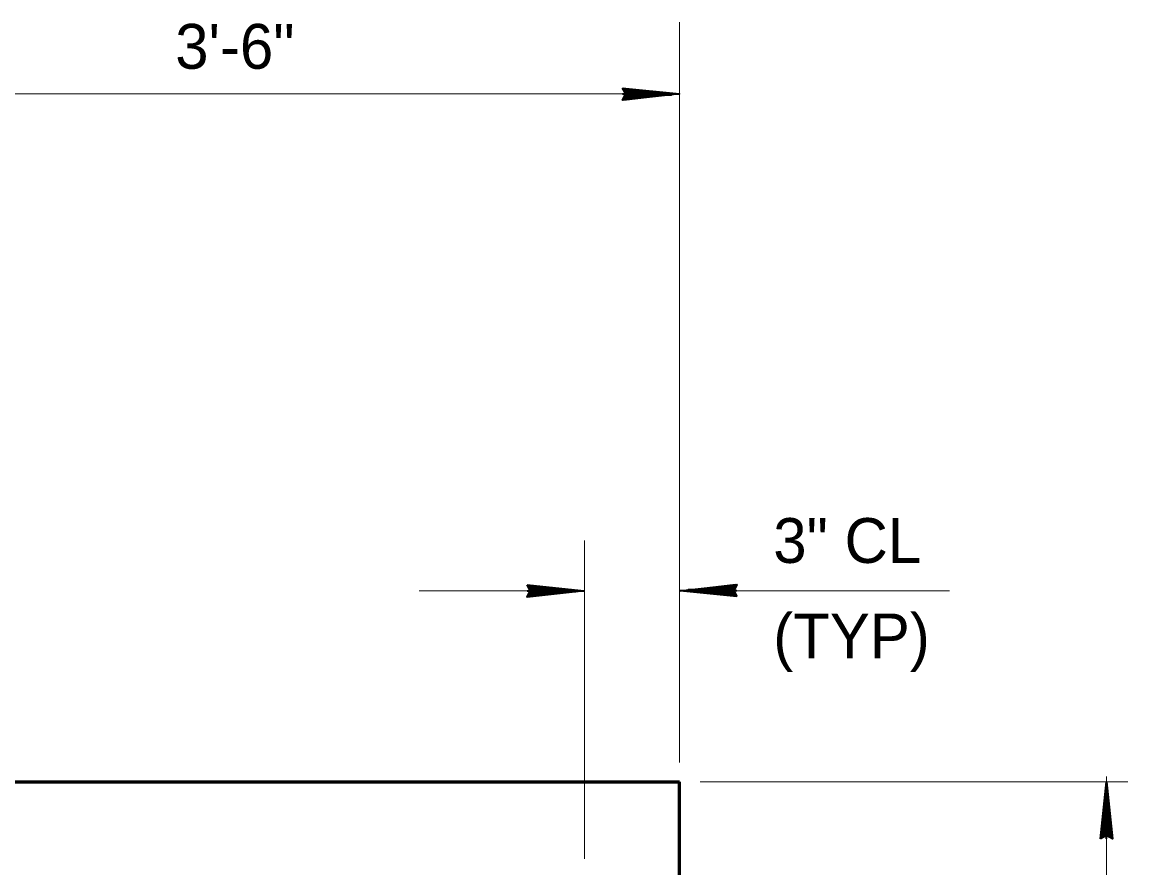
# Model space of a CAD drawing. Extents: x 14.14 to 17.34, y -1.61 to 0.38.
# Drawn here: x 16.3775 to 16.583, y 0.0521 to 0.2092 of the extents above; entities that cross this region are included whole.
import ezdxf

# ---------------------------------------------------------------- set-up
doc = ezdxf.new("R2010")
doc.units = 0
doc.header["$LTSCALE"] = 0.0033
doc.layers.add('1', color=7, linetype='Continuous', lineweight=40)

msp = doc.modelspace()

# ---------------------------------------------------------------- linework, layer by layer
at = {"layer": '1', "lineweight": 13}
for p, q in [((16.499667, 0.071667), (16.499667, 0.20925)), ((16.000417, 0.195917), (16.499083, 0.195917)), ((16.482, 0.05375), (16.482, 0.112917)), ((16.45125, 0.103583), (16.472083, 0.103583)), ((16.5095, 0.103583), (16.549833, 0.103583)), ((16.5035, 0.068083), (16.583, 0.068083)), ((16.579, 0.069083), (16.579, -0.01425))]:
    msp.add_line(p, q, dxfattribs=at)
at = {"layer": '1', "lineweight": 35}
for p, q in [((16.489083, 0.195917), (16.499667, 0.195917)), ((16.48925, 0.19525), (16.496583, 0.196)), ((16.489333, 0.196917), (16.497167, 0.196)), ((16.489333, 0.196917), (16.497167, 0.196)), ((16.489333, 0.196833), (16.497167, 0.196)), ((16.489333, 0.19675), (16.497167, 0.195917)), ((16.489333, 0.19675), (16.497167, 0.19575)), ((16.489333, 0.195083), (16.496667, 0.195917)), ((16.489333, 0.195), (16.496667, 0.19575)), ((16.489333, 0.194833), (16.496667, 0.195667)), ((16.471333, 0.103583), (16.481917, 0.103583)), ((16.4715, 0.102917), (16.478833, 0.103667)), ((16.471583, 0.104583), (16.479417, 0.103667)), ((16.471583, 0.104583), (16.479417, 0.103667)), ((16.471583, 0.1045), (16.479417, 0.103667)), ((16.471583, 0.104417), (16.479417, 0.103583)), ((16.471583, 0.104417), (16.479417, 0.103417)), ((16.471583, 0.10275), (16.478917, 0.103583)), ((16.471583, 0.102667), (16.478917, 0.103417)), ((16.471583, 0.1025), (16.478917, 0.103333)), ((16.510333, 0.103583), (16.49975, 0.103583)), ((16.510083, 0.10275), (16.50225, 0.10375)), ((16.510083, 0.10275), (16.50225, 0.103583)), ((16.510083, 0.102583), (16.50225, 0.1035)), ((16.510083, 0.102583), (16.50225, 0.1035)), ((16.510083, 0.102667), (16.50225, 0.1035)), ((16.510083, 0.104667), (16.50275, 0.103833)), ((16.510083, 0.1045), (16.50275, 0.10375)), ((16.510083, 0.104417), (16.50275, 0.103583)), ((16.510167, 0.10425), (16.502833, 0.1035)), ((16.579, 0.0575), (16.579, 0.068083)), ((16.578, 0.05775), (16.578917, 0.065583)), ((16.578, 0.05775), (16.578917, 0.065583)), ((16.578083, 0.05775), (16.578917, 0.065583)), ((16.578167, 0.05775), (16.579, 0.065583)), ((16.578167, 0.05775), (16.579167, 0.065583)), ((16.579667, 0.057667), (16.578917, 0.065)), ((16.579833, 0.05775), (16.579, 0.065083)), ((16.579917, 0.05775), (16.579167, 0.065083)), ((16.580083, 0.05775), (16.57925, 0.065083))]:
    msp.add_line(p, q, dxfattribs=at)
for points in [[(16.489083, 0.197), (16.499667, 0.195917), (16.489083, 0.19475), (16.489667, 0.195917)], [(16.489833, 0.196), (16.4945, 0.196083), (16.4945, 0.196), (16.493583, 0.196), (16.489833, 0.196083), (16.492833, 0.196167), (16.489667, 0.19625), (16.491917, 0.196333), (16.489667, 0.196417), (16.493167, 0.196167), (16.497833, 0.196), (16.496917, 0.19575), (16.498167, 0.19575), (16.489833, 0.19575), (16.49225, 0.195583), (16.489667, 0.195583), (16.495, 0.196), (16.489667, 0.195333)], [(16.471333, 0.104667), (16.481917, 0.103583), (16.471333, 0.102417), (16.471917, 0.103583)], [(16.472083, 0.103667), (16.47675, 0.10375), (16.47675, 0.103667), (16.475833, 0.103667), (16.472083, 0.10375), (16.475083, 0.103833), (16.471917, 0.103917), (16.474167, 0.104), (16.471917, 0.104083), (16.475417, 0.103833), (16.480083, 0.103667), (16.479167, 0.103417), (16.480417, 0.103417), (16.472083, 0.103417), (16.4745, 0.10325), (16.471917, 0.10325), (16.47725, 0.103667), (16.471917, 0.103)], [(16.510333, 0.1025), (16.49975, 0.103583), (16.510333, 0.10475), (16.50975, 0.103583)], [(16.509583, 0.1035), (16.504917, 0.103417), (16.504917, 0.1035), (16.505833, 0.1035), (16.509583, 0.103417), (16.506583, 0.103333), (16.50975, 0.10325), (16.5075, 0.103167), (16.50975, 0.103083), (16.50625, 0.103333), (16.501583, 0.1035), (16.5025, 0.10375), (16.50125, 0.10375), (16.509583, 0.10375), (16.507167, 0.103917), (16.50975, 0.103917), (16.504417, 0.1035), (16.50975, 0.104167)], [(16.577917, 0.0575), (16.579, 0.068083), (16.580167, 0.0575), (16.579, 0.058083)], [(16.578917, 0.05825), (16.578833, 0.062917), (16.578917, 0.062917), (16.578917, 0.062), (16.578833, 0.05825), (16.57875, 0.06125), (16.578667, 0.058083), (16.578583, 0.060333), (16.5785, 0.058083), (16.57875, 0.061583), (16.578917, 0.06625), (16.579167, 0.065333), (16.579167, 0.066583), (16.579167, 0.05825), (16.579333, 0.060667), (16.579333, 0.058083), (16.578917, 0.063417), (16.579583, 0.058083)]]:
    msp.add_lwpolyline(points, close=True, dxfattribs=at)
for points in [[(16.489833, 0.196), (16.489417, 0.19675), (16.489667, 0.1965), (16.489833, 0.196167), (16.490083, 0.19625), (16.489917, 0.196583), (16.48975, 0.195833), (16.489583, 0.195333), (16.489333, 0.194917)], [(16.472083, 0.103667), (16.471667, 0.104417), (16.471917, 0.104167), (16.472083, 0.103833), (16.472333, 0.103917), (16.472167, 0.10425), (16.472, 0.1035), (16.471833, 0.103), (16.471583, 0.102583)], [(16.509583, 0.1035), (16.51, 0.10275), (16.50975, 0.103), (16.509583, 0.103333), (16.509333, 0.10325), (16.5095, 0.102917), (16.509667, 0.103667), (16.509833, 0.104167), (16.510083, 0.104583)], [(16.578917, 0.05825), (16.578167, 0.057833), (16.578417, 0.058083), (16.57875, 0.05825), (16.578667, 0.0585), (16.578333, 0.058333), (16.579083, 0.058167), (16.579583, 0.058), (16.58, 0.05775)]]:
    msp.add_lwpolyline(points, dxfattribs=at)
at = {"layer": '1', "lineweight": 60}
for points in [[(16.333, 0.17225), (16.333, 0.068083), (16.499667, 0.068083)], [(15.999667, -0.01525), (16.499667, -0.01525), (16.499667, 0.068083)]]:
    msp.add_lwpolyline(points, dxfattribs=at)

# ---------------------------------------------------------------- texts
at = {"layer": '1'}
for s, height, p in [('3\'-6"', 0.008333, (16.405917, 0.200583)), ('3" CL', 0.008334, (16.517083, 0.10875)), ('(TYP)', 0.008334, (16.517083, 0.091))]:
    msp.add_text(s, height=height, dxfattribs=at).set_placement(p)

doc.saveas('drawing.dxf')
